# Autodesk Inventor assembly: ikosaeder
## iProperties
Created: 2007-01
Part Number: ikosaeder
Cost Center: 0,48 kg
Document SubType Name: Assembly
Designer: M. Fiedler
SaveDate: 2007-01-24
SaveTime: 23:02
FileName: ikosaeder
Masse: 0,48 kg
Author: M. Fiedler
